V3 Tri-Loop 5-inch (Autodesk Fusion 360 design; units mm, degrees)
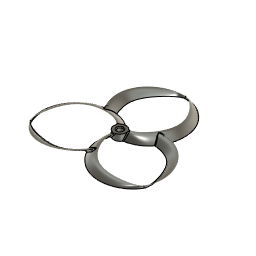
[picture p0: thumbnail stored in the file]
sketch "Hub 5mm Shaft" plane through (0, 0, 0) normal (0, 0, 1) x axis (1, 0, 0)
  circle C1 centre (0, 0) radius 2.6
  circle C2 centre (0, 0) radius 6
  point P1 (0, 0)
  point P2 (0, 0)
  coincident P1 P2
  concentric C1 C2
  dimension "d28" diameter C1 = 5.2
  dimension "d29" diameter C2 = 12
extrude "Extrude2" new body sketch "Hub 5mm Shaft" along normal blind 6 bodies "Hub 5mm Shaft"
work_plane "WorkPlane9" AlongDistance 2.5
work_plane "WorkPlane10" AlongDistance -2.5
sketch "Profile Start" plane through (2.5, 0, 0) normal (1, 0, 0) x axis (0, 1, 0)
  line L1 (-2, 0) -> (-3, 0)
  curve K1 (-3, 0) -> (-2, 0)
  curve K2 (-4, -1.5) -> (-2, 1.5)
  curve K3 (-1, 1.5) -> (-3, -1.5)
  curve K4 (2.7, 6) -> (3.3, 6)
  point P2 (-3, 0)
  point P4 (-2, 0)
  point P3 (3, 6)
  point P1 (0, 0)
  point P5 (-2, 1.5)
  point P8 (-1, 1.5)
  point P9 (3.3, 6)
  point P10 (2.7, 6)
  horizontal L1
  midpoint P2 K2
  midpoint P4 K3
  midpoint P3 K4
  dimension "d65" distance P1 P3 = 3
  dimension "d66" distance P1 P3 = 6
  dimension "d67" distance P1 P2 = 3
  dimension "d68" distance P2 P5 = 1
  dimension "d69" distance P2 P5 = 1.5
  dimension "d70" distance P4 P8 = 1.5
  dimension "d71" distance P5 P8 = 1
  dimension "d72" distance P9 P10 = 0.6
  dimension "d134" distance P2 P4 = 1
sketch "Profile End" plane through (-2.5, 0, 0) normal (1, 0, 0) x axis (0, 1, 0)
  curve K1 (3, 0) -> (2.2, 0)
  curve K2 (1.5, 1.5) -> (3.3181, -1.2241)
  curve K3 (-1.75, 5) -> (-2.25, 5)
  curve K4 (4, -1.5) -> (2, 1.5)
  line L1 (-1.75, 5) -> (-2.25, 5)
  line L2 (2.2, 0) -> (3, 0)
  point P5 (-1.75, 5)
  point P9 (-2.25, 5)
  point P4 (2.2, 0)
  point P8 (3, 0)
  point P6 (-2, 5)
  point P11 (0, 0)
  point P3 (1.5, 1.5)
  point P7 (2, 1.5)
  dimension "d84" distance P5 P9 = 0.5
  dimension "d89" distance P4 P8 = 0.8
  dimension "d101" distance P6 P11 = 5
  dimension "d102" distance P6 P11 = 2
  dimension "d103" distance P8 P11 = 3
  dimension "d104" distance P3 P11 = 1.5
  dimension "d105" distance P3 P11 = 1.5
  dimension "d106" distance P7 P11 = 2
  dimension "d107" distance P7 P11 = 1.5
sketch "Target Shape" plane through (0, 0, 0) normal (0, 0, 1) x axis (1, 0, 0)
  line L1 (0, 50.8) -> (0, 0)
  line L2 (25.4, 25.4) -> (0, 25.4)
  line L3 (-25.4, 25.4) -> (0, 25.4)
  circle C1 centre (0, 0) radius 50.8
  circle C2 centre (0, 25.4) radius 25.4
  point P1 (0, 0)
  point P2 (0, 0)
  point P7 (0, 0)
  point P8 (0, 50.8)
  point P9 (0, 25.4)
  point P10 (0, 25.4)
  point P11 (25.4, 25.4)
  point P12 (0, 25.4)
  point P13 (-25.4, 25.4)
  coincident P1 P2
  coincident P2 P7
  coincident C1 P8
  midpoint L1 P9
  coincident P8 C2
  coincident P9 P10
  coincident C2 P11
  perpendicular L1 L2
  coincident P9 P12
  coincident C2 P13
  perpendicular L1 L3
  dimension "d95" diameter C1 = 101.6
sketch "Profile Edge" plane through (0, 0, 0) normal (1, 0, 0) x axis (0, 1, 0)
  line L1 (63.5, 0) -> (63, 0)
  curve K1 (63, 0) -> (63.5, 0)
  curve K2 (63.125, 2) -> (63.375, 2)
  curve K3 (63.5, 0.8) -> (63.5, -0.8)
  curve K4 (63, -0.8) -> (63, 0.8)
  point P4 (63.25, 2)
  point P3 (63.5, 0)
  point P2 (63, 0)
  point P1 (0, 0)
  point P5 (63.375, 2)
  point P6 (63.125, 2)
  horizontal L1
  midpoint P4 K2
  midpoint P3 K3
  midpoint P2 K4
  dimension "d96" distance P2 P3 = 0.5
  dimension "d98" distance P3 P4 = 2
  dimension "d121" distance P1 P4 = 2
  dimension "d138" distance P5 P6 = 0.25
  dimension "d177" distance P1 P3 = 63.5 (= "( 127 / 2 ) * 1 mm")
  dimension "d191" distance P3 P4 = 0.25
work_plane "WorkPlane11" AlongDistance 31.75 (= "( 127 / 4 ) * 1 mm")
sketch "Profile Mid" plane through (0, 31.75, 0) normal (0, 1, 0) x axis (1, 0, 0)
  line L1 (30.85, 0) -> (31.75, 0)
  curve K1 (30.85, 0) -> (31.75, 0)
  curve K2 (23.5, -5) -> (24, -5)
  curve K3 (32.85, 1.5) -> (28.85, -1.5)
  curve K4 (30.1093, -1.5) -> (33.3907, 1.5)
  line L2 (-24.65, 0) -> (-23.75, 0)
  curve K5 (-24.65, 0) -> (-23.75, 0)
  curve K6 (-25.6093, -1.5) -> (-21.8907, 1.5)
  curve K7 (-31.95, -5) -> (-31.55, -5)
  curve K8 (-22.65, 1.5) -> (-26.65, -1.5)
  point P3 (23.75, -5)
  point P4 (30.85, 0)
  point P2 (31.75, 0)
  point P15 (-31.75, -5)
  point P14 (-24.65, 0)
  point P11 (-23.75, 0)
  point P5 (24, -5)
  point P6 (23.5, -5)
  point P1 (0, 0)
  point P18 (-31.95, -5)
  point P19 (-31.55, -5)
  midpoint P3 K2
  midpoint P4 K3
  midpoint P2 K4
  midpoint P15 K7
  midpoint P14 K8
  midpoint P11 K6
  dimension "d109" distance P2 P4 = 0.9
  dimension "d110" distance P2 P3 = 5
  dimension "d111" distance P2 P3 = 8
  dimension "d112" distance P5 P6 = 0.5
  dimension "d113" distance P1 P2 = 31.75 (= "( 127 / 4 ) * 1 mm")
  dimension "d114" distance P11 P14 = 0.9
  dimension "d115" distance P11 P15 = 5
  dimension "d116" distance P11 P15 = 8
  dimension "d117" distance P18 P19 = 0.4
  dimension "d118" distance P1 P15 = 31.75 (= "( 127 / 4 ) * 1 mm")
sketch "Lower Rails" plane through (0, 0, 0) normal (0, 0, 1) x axis (1, 0, 0)
  curve K1 (-2.5, 2.2) -> (0.0002, 63.5006)
  curve K2 (2, 1.7) -> (-7, 2.7)
  curve K3 (-24.6593, 27.625) -> (-24.6407, 35.875)
  curve K4 (-1.4998, 63.4997) -> (1.5002, 63.5015)
  curve K5 (-2.5, 3) -> (0, 63)
  curve K6 (2, 2.5) -> (-7, 3.5)
  curve K7 (-23.7441, 28.1275) -> (-23.7559, 35.3725)
  curve K8 (-1.5, 63) -> (1.5, 63)
  curve K9 (0, 63.5005) -> (2.5, -3)
  curve K10 (-6, 63.5005) -> (6, 63.5005)
  curve K11 (31.55, 37.75) -> (31.95, 25.75)
  curve K12 (9.7325, -2.2212) -> (-4.7325, -3.7788)
  arc A1 centre (-1.7871, 30.3832) radius 32.6657 clockwise from (0, 63) to (2.5, -2)
  point P8 (30.85, 31.75)
  point P9 (-24.65, 31.75)
  point P11 (-24.65, 31.75)
  point P10 (-2.5, 2.2)
  point P12 (-2.5, 2.2)
  point P32 (0.0002, 63.5006)
  point P5 (0, 63)
  point P19 (0, 63)
  point P20 (-23.75, 31.75)
  point P22 (-23.75, 31.75)
  point P4 (-2.5, 3)
  point P21 (-2.5, 3)
  point P31 (2.5, -3)
  point P33 (2.5, -3)
  point P30 (31.75, 31.75)
  point P34 (31.75, 31.75)
  point P35 (0, 63.5005)
  point P27 (1.5, 63)
  point P28 (-1.5, 63)
  point P17 (1.5002, 63.5015)
  point P18 (-1.4998, 63.4997)
  coincident P8 A1
  coincident P9 P11
  coincident P10 P12
  midpoint P12 K2
  midpoint P11 K3
  midpoint K4 P32
  coincident P5 P19
  coincident P20 P22
  coincident P4 P21
  midpoint P21 K6
  parallel K2 K6
  midpoint P20 K7
  midpoint P19 K8
  coincident P31 P33
  coincident P30 P34
  midpoint P35 K10
  midpoint P34 K11
  midpoint P33 K12
  dimension "d136" distance P27 P28 = 3
  dimension "d137" distance P17 P18 = 3
work_plane "WorkPlane12" AlongDistance 6
sketch "Upper Rails" plane through (0, 0, 6) normal (0, 0, 1) x axis (1, 0, 0)
  line L1 (0, 63.5) -> (0, 63)
  curve K1 (2.5, 3) -> (0, 63.25)
  curve K2 (-0.2, 3) -> (5.2, 3)
  curve K3 (23.7612, 27.6237) -> (23.7426, 35.8737)
  curve K4 (1.5, 63.25) -> (-1.5, 63.25)
  curve K5 (-2.5, -2) -> (0, 63.25)
  curve K6 (2, -2) -> (-7, -2)
  curve K7 (-5, 63.25) -> (5, 63.25)
  curve K8 (-31.8911, 26.8746) -> (-31.6097, 36.6246)
  point P7 (2.5, 3)
  point P9 (2.5, 3)
  point P6 (23.7519, 31.7487)
  point P5 (0, 63.25)
  point P16 (0, 63.25)
  point P18 (-2.5, -2)
  point P17 (-31.7504, 31.7496)
  point P14 (-1.5, 63.25)
  point P15 (1.5, 63.25)
  coincident P7 P9
  midpoint P7 K2
  midpoint P6 K3
  midpoint P5 K4
  coincident P5 P16
  midpoint P18 K6
  midpoint P16 K7
  midpoint P17 K8
  dimension "d135" distance P14 P15 = 3
loft "Loft3" sketch "Profile Start" + "Profile Mid" + "Profile Edge" bodies "Blade Template 5x2.5x3"
loft "Loft4" sketch "Profile Edge" + "Profile Mid" + "Profile End"
circular_pattern "C-Pattern2" TotalAngle 360
combine "Combine2" bodies "Blade Template 4x3x3 (1)"
offset_faces "OffsetFaces5" distance -0.5
circular_pattern "C-Pattern3" TotalAngle 360
combine "Combine3"
fillet "Fillet7" radius 1
circular_pattern "C-Pattern4" TotalAngle 360 bodies "Blade Template 4x3x3 (2)", "Blade Template 4x3x3 (3)"
combine "Combine8" bodies "Blade Template 4x3x3 (2)", "Blade Template 4x3x3 (3)"
chamfer "Chamfer1" distance 0.75
copy_paste_bodies "CopyPasteBodies1"
offset_faces "OffsetFaces3" distance 2
combine "Combine4"
fillet "Fillet8" radius 1
offset_faces "OffsetFaces4" distance -2
mirror "Mirror1" mirrorStitchTolerance 0.1 bodies "5x2.5x3 CW"
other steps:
base_feature "Base Feature" bodies "Hub 5mm Shaft", "5x2.5x3 CCW"
named bodies: "Hub 5mm Shaft", "Blade Template 5x2.5x3", "5x2.5x3 CCW", "5x2.5x3 CW", "Blade Template 4x3x3 (1)", "Blade Template 4x3x3 (2)", "Blade Template 4x3x3 (3)"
